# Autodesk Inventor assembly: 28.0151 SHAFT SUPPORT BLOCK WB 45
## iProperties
Created: 2007-06
Part Number: 28.0151 SHAFT SUPPORT BLOCK WB 45
Document SubType Name: Assembly
Designer: Andy Moles
Author: Andy Moles
